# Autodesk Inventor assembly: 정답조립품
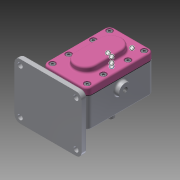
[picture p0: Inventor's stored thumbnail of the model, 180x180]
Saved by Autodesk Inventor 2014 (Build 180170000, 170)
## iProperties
Created: 2020-04
Part Number: 정답조립품
Document SubType Name: Assembly
Designer: kh
Author: kh
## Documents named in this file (11)
- C:\Users\kh\Desktop\700407V1058\답안조립품.iam
- C:\Users\kh\Desktop\700407V1058\본체.ipt
- C:\Users\kh\Desktop\700407V1058\Ű 6 x 6 x 18.ipt
- C:\Users\kh\Desktop\700407V1058\개스킷.ipt
- C:\Users\kh\Desktop\700407V1058\메인축.ipt
- C:\Users\kh\Desktop\700407V1058\베어링부시.ipt
- C:\Users\kh\Desktop\700407V1058\볼트 M5.ipt
- C:\Users\kh\Desktop\700407V1058\서브축.ipt
- C:\Users\kh\Desktop\700407V1058\스퍼기어.ipt
- C:\Users\kh\Desktop\700407V1058\오일 실 16 28 7.ipt
- C:\Users\kh\Desktop\700407V1058\커버.ipt
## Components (3 placed, 2 different names)
1. 개스킷:1 — 플러쉬:1, 플러쉬:2
2. Ű 6 x 6 x 18:1 — 각도:1
3. Ű 6 x 6 x 18:2 — 각도:2
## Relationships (4: Angle 2, Flush 2)
- 각도:1 [Angle]: Ű 6 x 6 x 18:1
- 각도:2 [Angle]: Ű 6 x 6 x 18:2
- 플러쉬:1 [Flush]: 개스킷:1
- 플러쉬:2 [Flush]: 개스킷:1
